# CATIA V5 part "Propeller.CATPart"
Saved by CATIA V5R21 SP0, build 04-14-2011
Part number: Propeller
Bounding box of the stored display mesh (mm): x -171.33 to 170, y 0 to 166.783, z -171.002 to 170.981
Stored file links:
  C:\Users\riadm\Desktop\Jet_Engine\Propeller.CATPart
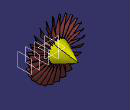
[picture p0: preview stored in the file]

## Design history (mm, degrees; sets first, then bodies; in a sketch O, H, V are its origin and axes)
Body1 (main body)
  Sketch1 on yz-plane, origin (0, 0, 0), H (0, 1, 0), V (0, 0, 1)
    point P1 (0, 20)
    line L1 (0, 20) -> (0, 63.5)
    line L2 (0, 63.5) -> (36.783, 63.5)
    line L3 (36.783, 63.5) -> (166.783, 0)
    point P4 (166.783, 0)
    line L4 (166.783, 0) -> (40, 0)
    line L5 (40, 0) -> (40, 20)
    line L6 (40, 20) -> (0, 20)
    distance L2 H = 63.5
    length L2 = 36.783
    length L3 H = 130
    length L5 = 20
    length L6 = 40
    coincidence: P1 V, P4 H
    vertical: L1 V, L5 V
    horizontal: L2 H, L4 H, L6 H
  Shaft1: profile Sketch1, axis Sketch1.L4, angle 360
  Plane1: type Offset, RefPlane yz-plane, Offset 64
  Sketch2 on Plane1, origin (64, 0, 0), H (0, 1, 0), V (0, 0, 1)
    arc A1 centre (25.7664, -29.0236) radius 28.757 from (7, -7.234) to (43.8597, -6.672) cw
    point P2 (7, -7.234)
    point P3 (43.8597, -6.672)
    arc A2 centre (26.0873, -50.0742) radius 46.9 from (7, -7.234) to (43.8597, -6.672) cw
    radius A1 = 28.757
    radius A2 = 46.9
    distance P2 H = 7.234
    distance P2 V = 7
    distance P3 H = 6.672
    distance P3 P2 = 36.864
  Pad1: profile Sketch2, direction (1, 0, 0), up to the existing solid (limit type 2)
  Plane2: type Offset, RefPlane yz-plane, Offset 120
  Sketch3 on Plane2, origin (120, 0, 0), H (0, 1, 0), V (0, 0, 1)
    arc A1 centre (11.6484, -32.5137) radius 36.954 from (7.245, 4.177) to (44.767, -16.12) cw
    point P2 (7.245, 4.177)
    point P3 (44.767, -16.12)
    arc A2 centre (0.2522, -53.5812) radius 58.18 from (7.245, 4.177) to (44.767, -16.12) cw
    radius A1 = 36.954
    radius A2 = 58.18
    distance P2 H = 4.177
    distance P2 V = 7.245
    distance P3 H = 16.12
    distance P3 P2 H = 37.522
  Plane3: type Offset, RefPlane yz-plane, Offset 170
  Sketch4 on Plane3, origin (170, 0, 0), H (0, 1, 0), V (0, 0, 1)
    arc A1 centre (-2.5708, -28.6462) radius 40.64 from (4.815, 11.317) to (37.401, -21.307) cw
    point P2 (4.815, 11.317)
    point P3 (37.401, -21.307)
    arc A2 centre (-20.7657, -46.82) radius 63.516 from (4.815, 11.317) to (37.401, -21.307) cw
    radius A1 = 40.64
    radius A2 = 63.516
    distance P2 V = 4.815
    distance P2 H = 11.317
    distance P2 P3 H = 32.586
    distance P3 H = 21.307
  Circle1 to Circle6: stored without definition
  Curve1: Elements (vertex of Circle1; vertex of Circle3; vertex of Circle5)
  Curve2: Elements (vertex of Circle1; vertex of Circle3; vertex of Circle5)
  Join1: Elements (Circle2; Circle1)
  Join2: Elements (Circle4; Circle3)
  Join3: Elements (Circle6; Circle5)
  Loft1: Sections (Join1; Join2; Join3), Guides (Curve1; Curve2)
  Fill1: Boundary (edge of Loft1; edge of Loft1)
  Fill2: Boundary (edge of Loft1; edge of Loft1)
  Join4: Elements (Fill2; Loft1; Fill1)
  CloseSurface1: CloseElement Join4
  CircPattern1: of Pad1, instances 26, angular step 14.4, axis from Y axis
  CircPattern2: of CloseSurface1, instances 26, angular step 14.4, axis from Y axis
